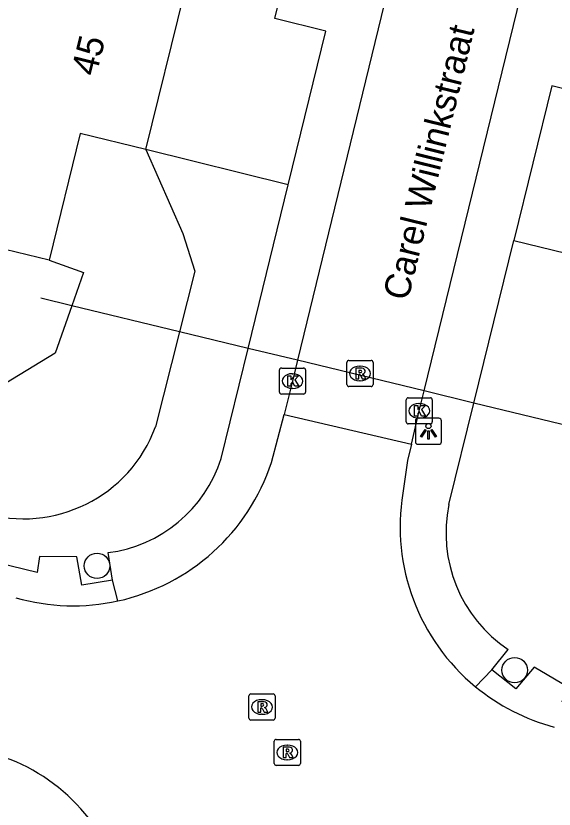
# Model space of a CAD drawing. Extents: x 163268 to 164360, y 381529 to 382285.
# Drawn here: x 163854.48 to 163875.14, y 382163.66 to 382194.1 of the extents above; entities that cross this region are included whole.
import ezdxf

# ---------------------------------------------------------------- set-up
doc = ezdxf.new("R2010")
doc.units = 0
for name, color, linetype in [('IMGEO_Boom', 7, 'Continuous'), ('IMGEO_Duiker', 7, 'Continuous'), ('IMGEO_Groenvoorziening', 7, 'Continuous'), ('IMGEO_Kolk', 7, 'Continuous'), ('IMGEO_Lichtpunt', 7, 'Continuous'), ('IMGEO_Openbare_ruimte_label', 7, 'Continuous'), ('IMGEO_Pand', 7, 'Continuous'), ('IMGEO_Pand_nummerreeks', 7, 'Continuous'), ('IMGEO_Rijbaan_lokaal_open', 7, 'Continuous'), ('IMGEO_Rioolput', 7, 'Continuous'), ('IMGEO_Voetpad_open', 7, 'Continuous'), ('IMGEO_Waterloop', 7, 'Continuous')]:
    doc.layers.add(name, color=color, linetype=linetype)

msp = doc.modelspace()

# ---------------------------------------------------------------- linework, layer by layer
at = {"layer": 'IMGEO_Boom'}
for centre in [(163857.593, 382172.999), (163873.623, 382168.996)]:
    msp.add_circle(centre, 0.489, dxfattribs=at)
at = {"layer": 'IMGEO_Duiker'}
msp.add_lwpolyline([(163881.02, 382177.076), (163879.055, 382177.552), (163872.058, 382179.245), (163870.145, 382179.708), (163865.288, 382180.883), (163863.395, 382181.341), (163860.761, 382181.979), (163856.627, 382182.979), (163855.429, 382183.269)], dxfattribs=at)
at = {"layer": 'IMGEO_Groenvoorziening'}
for points in [[(163864.927, 382187.613), (163859.471, 382188.966)], [(163859.471, 382188.966), (163860.888, 382185.749), (163861.35, 382184.302), (163860.761, 382181.979), (163859.837, 382178.336)], [(163873.595, 382185.486), (163879.108, 382184.137)]]:
    msp.add_lwpolyline(points, dxfattribs=at)
msp.add_arc((163854.774, 382180.2), 5.396, 253.0885, 339.7856, dxfattribs=at)
at = {"layer": 'IMGEO_Kolk'}
for p, q in [((163864.592, 382179.662), (163864.592, 382180.514)), ((163864.667, 382180.588), (163865.519, 382180.588)), ((163865.593, 382180.514), (163865.593, 382179.662)), ((163865.08, 382180.368), (163865.105, 382180.368)), ((163865.519, 382179.588), (163864.667, 382179.588)), ((163865.103, 382179.808), (163865.078, 382179.808)), ((163869.458, 382178.518), (163869.458, 382179.37)), ((163869.533, 382179.444), (163870.385, 382179.444)), ((163870.459, 382179.37), (163870.459, 382178.518)), ((163869.946, 382179.224), (163869.971, 382179.224)), ((163869.969, 382178.664), (163869.944, 382178.664)), ((163870.385, 382178.444), (163869.533, 382178.444))]:
    msp.add_line(p, q, dxfattribs=at)
for points in [[(163864.592, 382179.662), (163864.592, 382180.514)], [(163864.667, 382180.588), (163865.519, 382180.588)], [(163865.593, 382180.514), (163865.593, 382179.662)], [(163864.913, 382180.288), (163865.036, 382180.288), (163865.036, 382180.137), (163865.166, 382180.288), (163865.33, 382180.288), (163865.184, 382180.137), (163865.337, 382179.888), (163865.185, 382179.888), (163865.1, 382180.052), (163865.036, 382179.985), (163865.036, 382179.888), (163864.913, 382179.888), (163864.913, 382180.288)], [(163865.519, 382179.588), (163864.667, 382179.588)], [(163869.458, 382178.518), (163869.458, 382179.37)], [(163869.533, 382179.444), (163870.385, 382179.444)], [(163870.459, 382179.37), (163870.459, 382178.518)], [(163869.779, 382179.144), (163869.902, 382179.144), (163869.902, 382178.993), (163870.032, 382179.144), (163870.196, 382179.144), (163870.05, 382178.993), (163870.203, 382178.744), (163870.051, 382178.744), (163869.966, 382178.908), (163869.902, 382178.841), (163869.902, 382178.744), (163869.779, 382178.744), (163869.779, 382179.144)], [(163870.385, 382178.444), (163869.533, 382178.444)]]:
    msp.add_lwpolyline(points, dxfattribs=at)
for centre, start, end in [((163864.669, 382180.512), 91.552, 178.448), ((163864.669, 382180.512), 91.552, 178.448), ((163865.517, 382180.512), 1.552, 88.448), ((163865.517, 382180.512), 1.552, 88.448), ((163864.669, 382179.664), 181.552, 268.448), ((163864.669, 382179.664), 181.552, 268.448), ((163865.517, 382179.664), 271.552, 358.448), ((163865.517, 382179.664), 271.552, 358.448), ((163869.535, 382179.368), 91.552, 178.448), ((163869.535, 382179.368), 91.552, 178.448), ((163870.383, 382179.368), 1.552, 88.448), ((163870.383, 382179.368), 1.552, 88.448), ((163869.535, 382178.52), 181.552, 268.448), ((163869.535, 382178.52), 181.552, 268.448), ((163870.383, 382178.52), 271.552, 358.448), ((163870.383, 382178.52), 271.552, 358.448)]:
    msp.add_arc(centre, 0.0765, start, end, dxfattribs=at)
for centre, major_axis, ratio, start_param, end_param in [((163865.079, 382180.088), (-0.387, 0.002), 0.722429, 4.712389, 7.853982), ((163865.104, 382180.088), (-0.39, 0.002), 0.717154, 1.570796, 4.712389), ((163869.945, 382178.944), (-0.387, 0.002), 0.722429, 4.712389, 7.853982), ((163869.97, 382178.944), (-0.39, 0.002), 0.717154, 1.570796, 4.712389)]:
    msp.add_ellipse(centre, major_axis=major_axis, ratio=ratio, start_param=start_param, end_param=end_param, dxfattribs=at)
at = {"layer": 'IMGEO_Lichtpunt'}
for p, q in [((163870.717, 382178.658), (163869.909, 382178.658)), ((163870.717, 382178.658), (163869.909, 382178.658)), ((163869.815, 382178.563), (163869.815, 382177.756)), ((163869.815, 382178.563), (163869.815, 382177.756)), ((163870.811, 382177.756), (163870.811, 382178.563)), ((163870.811, 382177.756), (163870.811, 382178.563)), ((163869.909, 382177.662), (163870.717, 382177.662)), ((163869.909, 382177.662), (163870.717, 382177.662))]:
    msp.add_line(p, q, dxfattribs=at)
for points in [[(163870.189, 382178.227), (163870.228, 382178.199), (163870.04, 382177.937), (163870.002, 382177.964), (163870.189, 382178.227)], [(163870.291, 382178.179), (163870.338, 382178.179), (163870.338, 382177.857), (163870.291, 382177.857), (163870.291, 382178.179)], [(163870.401, 382178.199), (163870.439, 382178.226), (163870.626, 382177.964), (163870.587, 382177.936), (163870.401, 382178.199)]]:
    msp.add_lwpolyline(points, dxfattribs=at)
msp.add_circle((163870.314, 382178.361), 0.0994, dxfattribs=at)
for centre, start, end in [((163869.909, 382178.563), 90, 180), ((163869.909, 382178.563), 90, 180), ((163870.717, 382178.563), 0, 90), ((163870.717, 382178.563), 0, 90), ((163869.909, 382177.756), 180, 270), ((163869.909, 382177.756), 180, 270), ((163870.717, 382177.756), 270, 0), ((163870.717, 382177.756), 270, 360)]:
    msp.add_arc(centre, 0.0946, start, end, dxfattribs=at)
at = {"layer": 'IMGEO_Pand'}
for points in [[(163859.471, 382188.966), (163860.934, 382194.939), (163859.232, 382195.356)], [(163859.471, 382188.966), (163856.942, 382189.584), (163855.751, 382184.72)], [(163855.751, 382184.72), (163850.252, 382186.054), (163850.46, 382186.934)]]:
    msp.add_lwpolyline(points, dxfattribs=at)
at = {"layer": 'IMGEO_Rijbaan_lokaal_open'}
for points in [[(163868.973, 382196.036), (163865.288, 382180.883), (163865.094, 382180.087), (163864.773, 382178.809)], [(163869.659, 382177.662), (163869.958, 382178.945), (163870.145, 382179.708), (163873.864, 382194.892)], [(163864.288, 382176.968), (163864.773, 382178.809)], [(163864.773, 382178.809), (163869.659, 382177.662)], [(163869.659, 382177.662), (163869.514, 382177.04), (163869.332, 382175.785)]]:
    msp.add_lwpolyline(points, dxfattribs=at)
for centre, radius, start, end in [((163856.676, 382179.481), 8.016, 282.3887, 341.7274), ((163877.176, 382174.494), 7.95, 170.6511, 230.5134), ((163856.676, 382179.479), 8.013, 254.0675, 282.3965), ((163877.18, 382174.507), 7.962, 230.5553, 255.1354), ((163851.661, 382158.951), 7.108, 12.7722, 74.4361)]:
    msp.add_arc(centre, radius, start, end, dxfattribs=at)
at = {"layer": 'IMGEO_Rioolput'}
for p, q in [((163867.184, 382179.953), (163867.184, 382180.805)), ((163867.259, 382180.879), (163868.111, 382180.879)), ((163868.185, 382180.805), (163868.185, 382179.953)), ((163867.672, 382180.659), (163867.697, 382180.659)), ((163868.111, 382179.879), (163867.259, 382179.879)), ((163867.695, 382180.099), (163867.67, 382180.099)), ((163863.423, 382167.157), (163863.423, 382168.009)), ((163863.498, 382168.083), (163864.35, 382168.083)), ((163864.424, 382168.009), (163864.424, 382167.157)), ((163863.911, 382167.863), (163863.936, 382167.863)), ((163864.35, 382167.083), (163863.498, 382167.083)), ((163863.934, 382167.303), (163863.909, 382167.303)), ((163864.395, 382165.414), (163864.395, 382166.266)), ((163864.47, 382166.34), (163865.322, 382166.34)), ((163865.396, 382166.266), (163865.396, 382165.414)), ((163864.883, 382166.12), (163864.908, 382166.12)), ((163864.906, 382165.56), (163864.881, 382165.56)), ((163865.322, 382165.34), (163864.47, 382165.34))]:
    msp.add_line(p, q, dxfattribs=at)
for points in [[(163867.184, 382179.953), (163867.184, 382180.805)], [(163867.259, 382180.879), (163868.111, 382180.879)], [(163868.185, 382180.805), (163868.185, 382179.953)], [(163867.773, 382180.577), (163867.521, 382180.579), (163867.521, 382180.179)], [(163867.699, 382180.498), (163867.645, 382180.498), (163867.645, 382180.417)], [(163867.521, 382180.179), (163867.645, 382180.179), (163867.645, 382180.341), (163867.656, 382180.341)], [(163867.645, 382180.417), (163867.697, 382180.417)], [(163867.703, 382180.312), (163867.774, 382180.179), (163867.914, 382180.179), (163867.849, 382180.305)], [(163868.111, 382179.879), (163867.259, 382179.879)], [(163863.423, 382167.157), (163863.423, 382168.009)], [(163863.498, 382168.083), (163864.35, 382168.083)], [(163864.424, 382168.009), (163864.424, 382167.157)], [(163864.012, 382167.781), (163863.76, 382167.783), (163863.76, 382167.383)], [(163863.938, 382167.702), (163863.884, 382167.702), (163863.884, 382167.621)], [(163863.76, 382167.383), (163863.884, 382167.383), (163863.884, 382167.545), (163863.895, 382167.545)], [(163863.884, 382167.621), (163863.936, 382167.621)], [(163863.942, 382167.516), (163864.013, 382167.383), (163864.153, 382167.383), (163864.088, 382167.509)], [(163864.35, 382167.083), (163863.498, 382167.083)], [(163864.395, 382165.414), (163864.395, 382166.266)], [(163864.47, 382166.34), (163865.322, 382166.34)], [(163865.396, 382166.266), (163865.396, 382165.414)], [(163864.984, 382166.038), (163864.732, 382166.04), (163864.732, 382165.64)], [(163864.91, 382165.959), (163864.856, 382165.959), (163864.856, 382165.878)], [(163864.856, 382165.878), (163864.908, 382165.878)], [(163864.732, 382165.64), (163864.856, 382165.64), (163864.856, 382165.802), (163864.867, 382165.802)], [(163864.914, 382165.773), (163864.985, 382165.64), (163865.125, 382165.64), (163865.06, 382165.766)], [(163865.322, 382165.34), (163864.47, 382165.34)]]:
    msp.add_lwpolyline(points, dxfattribs=at)
for centre, radius, start, end in [((163867.261, 382180.803), 0.0765, 91.552, 178.448), ((163867.261, 382180.803), 0.0765, 91.552, 178.448), ((163868.109, 382180.803), 0.0765, 1.552, 88.448), ((163868.109, 382180.803), 0.0765, 1.552, 88.448), ((163867.705, 382180.402), 0.0964, 77.0061, 93.1865), ((163867.719, 382180.459), 0.0378, 276.6634, 79.6772), ((163867.772, 382180.467), 0.109, 350.3612, 89.416), ((163867.77, 382180.467), 0.112, 277.5842, 350.9817), ((163867.655, 382180.288), 0.0533, 26.0293, 88.6989), ((163867.681, 382180.606), 0.19, 274.7715, 282.9687), ((163867.754, 382180.252), 0.108, 29.5134, 73.7905), ((163867.261, 382179.955), 0.0765, 181.552, 268.448), ((163867.261, 382179.955), 0.0765, 181.552, 268.448), ((163868.109, 382179.955), 0.0765, 271.552, 358.448), ((163868.109, 382179.955), 0.0765, 271.552, 358.448), ((163863.5, 382168.007), 0.0765, 91.552, 178.448), ((163863.5, 382168.007), 0.0765, 91.552, 178.448), ((163864.348, 382168.007), 0.0765, 1.552, 88.448), ((163864.348, 382168.007), 0.0765, 1.552, 88.448), ((163863.944, 382167.606), 0.0964, 77.0061, 93.1865), ((163863.958, 382167.663), 0.0378, 276.6634, 79.6772), ((163864.011, 382167.671), 0.109, 350.3612, 89.416), ((163863.894, 382167.492), 0.0533, 26.0293, 88.6989), ((163863.92, 382167.81), 0.19, 274.7715, 282.9687), ((163864.009, 382167.671), 0.112, 277.5842, 350.9817), ((163863.993, 382167.456), 0.108, 29.5134, 73.7905), ((163863.5, 382167.159), 0.0765, 181.552, 268.448), ((163863.5, 382167.159), 0.0765, 181.552, 268.448), ((163864.348, 382167.159), 0.0765, 271.552, 358.448), ((163864.348, 382167.159), 0.0765, 271.552, 358.448), ((163864.472, 382166.264), 0.0765, 91.552, 178.448), ((163864.472, 382166.264), 0.0765, 91.552, 178.448), ((163865.32, 382166.264), 0.0765, 1.552, 88.448), ((163865.32, 382166.264), 0.0765, 1.552, 88.448), ((163864.892, 382166.067), 0.19, 274.7715, 282.9687), ((163864.916, 382165.863), 0.0964, 77.0061, 93.1865), ((163864.93, 382165.92), 0.0378, 276.6634, 79.6772), ((163864.983, 382165.928), 0.109, 350.3612, 89.416), ((163864.981, 382165.928), 0.112, 277.5842, 350.9817), ((163864.866, 382165.749), 0.0533, 26.0293, 88.6989), ((163864.965, 382165.713), 0.108, 29.5134, 73.7905), ((163864.472, 382165.416), 0.0765, 181.552, 268.448), ((163864.472, 382165.416), 0.0765, 181.552, 268.448), ((163865.32, 382165.416), 0.0765, 271.552, 358.448), ((163865.32, 382165.416), 0.0765, 271.552, 358.448)]:
    msp.add_arc(centre, radius, start, end, dxfattribs=at)
for centre, major_axis, ratio, start_param, end_param in [((163867.671, 382180.379), (-0.387, 0.002), 0.722429, 4.712389, 7.853982), ((163867.696, 382180.379), (-0.39, 0.002), 0.717154, 1.570796, 4.712389), ((163863.91, 382167.583), (-0.387, 0.002), 0.722429, 4.712389, 7.853982), ((163863.935, 382167.583), (-0.39, 0.002), 0.717154, 1.570796, 4.712389), ((163864.882, 382165.84), (-0.387, 0.002), 0.722429, 4.712389, 7.853982), ((163864.907, 382165.84), (-0.39, 0.002), 0.717154, 1.570796, 4.712389)]:
    msp.add_ellipse(centre, major_axis=major_axis, ratio=ratio, start_param=start_param, end_param=end_param, dxfattribs=at)
at = {"layer": 'IMGEO_Voetpad_open'}
for points in [[(163864.927, 382187.613), (163866.368, 382193.511), (163864.412, 382193.996), (163870.173, 382217.48)], [(163882.698, 382214.3), (163876.968, 382190.935), (163875.054, 382191.408), (163873.595, 382185.486)], [(163858.186, 382172.452), (163857.005, 382172.258), (163856.815, 382173.34), (163855.378, 382173.362), (163855.29, 382172.74), (163831.956, 382178.425), (163799.313, 382186.402), (163793.111, 382187.848)], [(163862.354, 382177.116), (163863.395, 382181.341), (163864.927, 382187.613)], [(163871.099, 382175.35), (163872.058, 382179.245), (163873.595, 382185.486)], [(163858.186, 382172.452), (163858.019, 382173.504)], [(163858.396, 382171.652), (163858.186, 382172.452)], [(163872.751, 382169.003), (163873.369, 382169.789)], [(163872.751, 382169.003), (163872.121, 382168.358)], [(163976.491, 382143.143), (163898.631, 382162.118), (163875.451, 382167.787), (163875.652, 382168.357), (163874.366, 382169.105), (163873.663, 382168.277), (163872.751, 382169.003)]]:
    msp.add_lwpolyline(points, dxfattribs=at)
for centre, radius, start, end in [((163857.347, 382178.718), 5.257, 277.3454, 342.258), ((163876.363, 382174.255), 5.376, 168.247, 236.1636)]:
    msp.add_arc(centre, radius, start, end, dxfattribs=at)
at = {"layer": 'IMGEO_Waterloop'}
msp.add_lwpolyline([(163855.751, 382184.72), (163857.074, 382184.258), (163856.627, 382182.979), (163855.99, 382181.153), (163853.515, 382179.66), (163840.646, 382182.469), (163829.917, 382185.005), (163815.626, 382188.515), (163803.182, 382191.841), (163801.892, 382191.922), (163797.444, 382192.463), (163794.602, 382193.737)], dxfattribs=at)

# ---------------------------------------------------------------- texts
at = {"layer": 'IMGEO_Openbare_ruimte_label'}
msp.add_text('Carel Willinkstraat', height=1, rotation=76.2279, dxfattribs=at).set_placement((163869.523, 382183.133))
at = {"layer": 'IMGEO_Pand_nummerreeks'}
msp.add_text('45', height=1, rotation=76.2372, dxfattribs=at).set_placement((163857.558, 382191.749))

doc.saveas('drawing.dxf')
